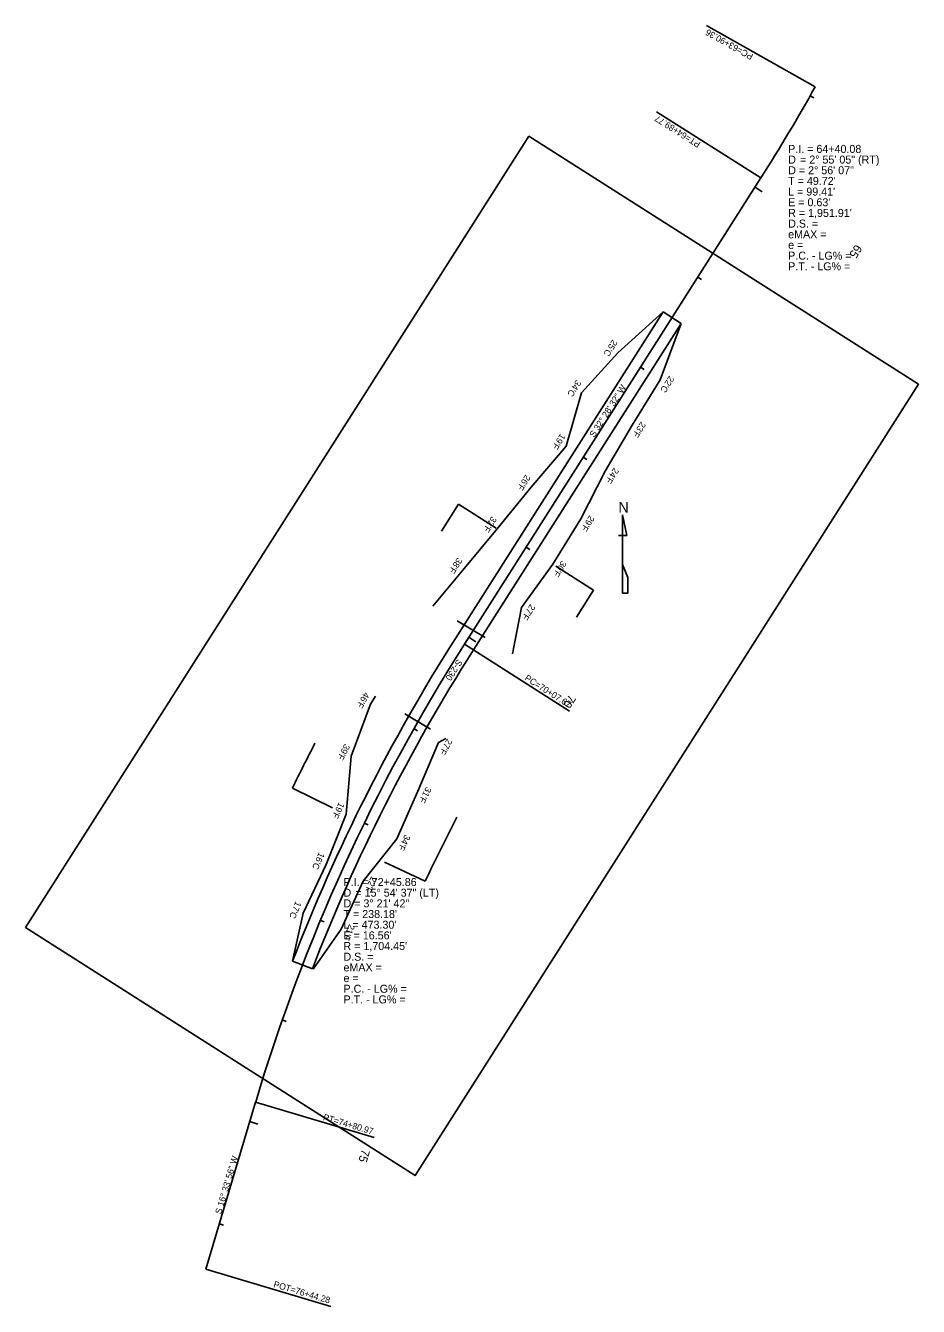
# Model space of a CAD drawing. Extents: x 1622419 to 1631737, y 887848 to 892020.
# Drawn here: x 1630900 to 1631737, y 887848 to 889048 of the extents above; entities that cross this region are included whole.
import ezdxf

# ---------------------------------------------------------------- set-up
doc = ezdxf.new("R2010")
doc.units = 0
for name, color, linetype in [('GN_Clip', 7, 'Continuous'), ('RD_EX_Misc', 7, 'Continuous'), ('RD_HC_Cl', 7, 'Continuous'), ('RD_HC_Data', 7, 'Continuous'), ('RD_HC_Data_Tic', 7, 'Continuous'), ('RD_HC_TX_Sta50', 7, 'Continuous'), ('RD_PD_Bridge', 7, 'Continuous'), ('RD_PD_CstnLmt', 7, 'Continuous'), ('RD_PD_CstnLmt_TX', 7, 'Continuous'), ('RD_PD_Final_TrvlWay', 7, 'Continuous'), ('RD_PD_RW', 7, 'Continuous'), ('RD_TX_RoadID', 7, 'Continuous')]:
    doc.layers.add(name, color=color, linetype=linetype)

msp = doc.modelspace()

# ---------------------------------------------------------------- linework, layer by layer
at = {"layer": 'GN_Clip'}
msp.add_lwpolyline([(1630899.9, 888203), (1631371.9, 888944.6), (1631737.1, 888712.2), (1631265.1, 887970.6)], close=True, dxfattribs=at)
at = {"layer": 'RD_EX_Misc'}
for p, q in [((1631463.7, 888570.4), (1631459.7, 888590)), ((1631459.7, 888590), (1631459.7, 888590)), ((1631459.7, 888590), (1631459.7, 888570.4)), ((1631455.8, 888570.4), (1631459.7, 888570.4)), ((1631459.7, 888543.2), (1631459.7, 888570.4)), ((1631459.7, 888570.4), (1631463.7, 888570.4)), ((1631463.7, 888570.4), (1631463.7, 888570.6)), ((1631464.6, 888531.2), (1631459.7, 888543.2)), ((1631459.7, 888543.2), (1631459.7, 888516.5)), ((1631464.6, 888516.5), (1631464.6, 888531.3)), ((1631464.6, 888531.3), (1631464.6, 888531.2)), ((1631459.7, 888516.5), (1631464.6, 888516.5))]:
    msp.add_line(p, q, dxfattribs=at)
at = {"layer": 'RD_HC_Cl'}
for p, q in [((1631589.5, 888905.6), (1631311.4, 888468.7)), ((1631115.6, 888039.4), (1631069, 887882.9))]:
    msp.add_line(p, q, dxfattribs=at)
for centre, radius, start, end in [((1629939.7, 889948.8), 1951.9, 327.6913, 330.6095), ((1632749.3, 887553.5), 1704.4, 147.5244, 163.4346)]:
    msp.add_arc(centre, radius, start, end, dxfattribs=at)
at = {"layer": 'RD_HC_Data'}
for p, q in [((1631640.4, 888990.9), (1631538.5, 889048.3)), ((1631589.5, 888905.6), (1631491.4, 888967.5)), ((1631311.4, 888468.7), (1631410, 888405.9)), ((1631115.6, 888039.4), (1631226.7, 888006.4)), ((1631069, 887882.9), (1631186, 887848.1))]:
    msp.add_line(p, q, dxfattribs=at)
at = {"layer": 'RD_HC_Data_Tic'}
for p, q in [((1631635.7, 888982.5), (1631639.2, 888980.5)), ((1631584, 888896.9), (1631590.7, 888892.6)), ((1631530.3, 888812.6), (1631533.6, 888810.4)), ((1631476.6, 888728.2), (1631479.9, 888726.1)), ((1631422.9, 888643.9), (1631426.3, 888641.7)), ((1631369.2, 888559.5), (1631372.6, 888557.3)), ((1631315.5, 888475.1), (1631322.2, 888470.8)), ((1631263.9, 888389.5), (1631267.4, 888387.5)), ((1631217.5, 888300.9), (1631221.1, 888299.2)), ((1631176.3, 888209.8), (1631180, 888208.3)), ((1631140.5, 888116.5), (1631144.3, 888115.1)), ((1631110.2, 888021.2), (1631117.8, 888018.9)), ((1631081.6, 887925.3), (1631085.5, 887924.2))]:
    msp.add_line(p, q, dxfattribs=at)
at = {"layer": 'RD_PD_Bridge'}
for p, q in [((1631304.6, 888490.6), (1631330.9, 888474.9)), ((1631255.4, 888403.5), (1631279.6, 888389))]:
    msp.add_line(p, q, dxfattribs=at)
at = {"layer": 'RD_PD_CstnLmt'}
for p, q in [((1631497.7, 888780), (1631455.3, 888741.8)), ((1631514.5, 888769.2), (1631495, 888716.5)), ((1631455.3, 888741.8), (1631421.3, 888704.1)), ((1631495, 888716.5), (1631468.8, 888673.9)), ((1631421.3, 888704.1), (1631406.7, 888654.1)), ((1631468.8, 888673.9), (1631443.5, 888630.8)), ((1631406.7, 888654.1), (1631374, 888615.7)), ((1631443.5, 888630.8), (1631420.5, 888586.1)), ((1631374, 888615.7), (1631342.2, 888576.6)), ((1631420.5, 888586.1), (1631394.2, 888543.5)), ((1631342.2, 888576.6), (1631310, 888537.9)), ((1631310, 888537.9), (1631281.8, 888504.2)), ((1631394.2, 888543.5), (1631365, 888502.9)), ((1631365, 888502.9), (1631356.4, 888459.7)), ((1631227.9, 888419.9), (1631223.4, 888412.3)), ((1631223.4, 888412.3), (1631205.3, 888363.8)), ((1631287.2, 888376.4), (1631267.7, 888331)), ((1631294, 888380.4), (1631287.2, 888376.4)), ((1631205.3, 888363.8), (1631200.4, 888309.3)), ((1631267.7, 888331), (1631247.9, 888286.1)), ((1631200.4, 888309.3), (1631181.8, 888262.2)), ((1631247.9, 888286.1), (1631216.4, 888246.6)), ((1631181.8, 888262.2), (1631160.3, 888216.5)), ((1631216.4, 888246.6), (1631195.9, 888201.6)), ((1631160.3, 888216.5), (1631150.2, 888171.7)), ((1631169.4, 888164.2), (1631195.9, 888201.6))]:
    msp.add_line(p, q, dxfattribs=at)
at = {"layer": 'RD_PD_Final_TrvlWay'}
for p, q in [((1631497.7, 888780), (1631302.9, 888474)), ((1631497.7, 888780), (1631514.5, 888769.2)), ((1631514.5, 888769.2), (1631319.8, 888463.3)), ((1631150.2, 888171.7), (1631168.8, 888164.5))]:
    msp.add_line(p, q, dxfattribs=at)
for radius in [1714.4, 1694.4]:
    msp.add_arc((1632749.3, 887553.5), radius, 147.5244, 158.8638, dxfattribs=at)
at = {"layer": 'RD_PD_RW'}
for p, q in [((1631305.9, 888599.8), (1631289.8, 888574.5)), ((1631341.3, 888577.2), (1631305.9, 888599.8)), ((1631397, 888541.8), (1631432.5, 888519.2)), ((1631432.5, 888519.2), (1631416.4, 888493.9)), ((1631150.1, 888333.8), (1631187.8, 888315.4)), ((1631274.5, 888246.5), (1631236.5, 888264.3))]:
    msp.add_line(p, q, dxfattribs=at)
for radius, end in [(1779.4, 153.9895), (1629.4, 154.8299)]:
    msp.add_arc((1632749.3, 887553.5), radius, 152.4785, end, dxfattribs=at)

# ---------------------------------------------------------------- texts
at = {"layer": 'RD_EX_Misc'}
msp.add_text('N', height=10, dxfattribs=at).set_placement((1631455.8, 888591.9))
at = {"layer": 'RD_HC_Data'}
for s, rotation, p in [('PC=63+90.36', 150.6095, (1631582.8, 889021.1)), ('PT=64+89.77', 147.6913, (1631533.4, 888938.6)), ('S 32%%d 28\' 32" W', 57.5244, (1631433.2, 888661.9)), ('PC=70+07.67', 327.5244, (1631367.3, 888435.4)), ('PT=74+80.97', 343.4346, (1631178.4, 888022.8)), ('S 16%%d 33\' 56" W', 73.4346, (1631083.2, 887934.1)), ('POT=76+44.28', 343.4346, (1631131.9, 887866.3))]:
    msp.add_text(s, height=6, rotation=rotation, dxfattribs=at).set_placement(p)
for s, p in [('P.I. = 64+40.08', (1631615, 888929)), ('D', (1631615, 888919)), ('    = 2%%d 55\' 05" (RT)', (1631615, 888919)), ('D = 2%%d 56\' 07"', (1631615, 888909)), ("T = 49.72'", (1631615, 888899)), ("L = 99.41'", (1631615, 888889)), ("E = 0.63'", (1631615, 888879)), ("R = 1,951.91'", (1631615, 888869)), ('D.S. = ', (1631615, 888859)), ('eMAX = ', (1631615, 888849)), ('e = ', (1631615, 888839)), ('P.C. - LG% = ', (1631615, 888829)), ('P.T. - LG% = ', (1631615, 888819)), ('P.I. = 72+45.86', (1631198, 888242)), ('D', (1631198, 888232)), ('    = 15%%d 54\' 37" (LT)', (1631198, 888232)), ('D = 3%%d 21\' 42"', (1631198, 888222)), ("T = 238.18'", (1631198, 888212)), ("L = 473.30'", (1631198, 888202)), ("E = 16.56'", (1631198, 888192)), ("R = 1,704.45'", (1631198, 888182)), ('D.S. = ', (1631198, 888172)), ('eMAX = ', (1631198, 888162)), ('e = ', (1631198, 888152)), ('P.C. - LG% = ', (1631198, 888142)), ('P.T. - LG% = ', (1631198, 888132))]:
    msp.add_text(s, height=7.5, dxfattribs=at).set_placement(p)
at = {"layer": 'RD_HC_TX_Sta50'}
for s, rotation, p in [('65', 237.5244, (1631678.2, 888843.8)), ('70', 237.5244, (1631409.7, 888422)), ('75', 253.4346, (1631215.3, 887995.9))]:
    msp.add_text(s, height=8, rotation=rotation, dxfattribs=at).set_placement(p)
at = {"layer": 'RD_PD_CstnLmt_TX'}
for s, rotation, p in [("25'C", 237.5244, (1631450.3, 888754.5)), ("22'C", 237.5244, (1631503.5, 888720.6)), ("34'C", 237.5244, (1631416.3, 888716.8)), ("23'F", 237.5244, (1631477, 888677.6)), ("19'F", 237.5244, (1631401.5, 888666.4)), ("24'F", 237.5244, (1631451.7, 888634.5)), ("26'F", 237.5244, (1631368.8, 888628)), ("32'F", 237.5244, (1631337, 888588.9)), ("29'F", 237.5244, (1631428.8, 888589.8)), ("38'F", 237.5244, (1631304.8, 888550.2)), ("30'F", 237.5244, (1631402.5, 888547.2)), ("27'F", 237.5244, (1631373.2, 888506.6)), ("46'F", 240.628, (1631217.6, 888424.2)), ("39'F", 242.3087, (1631199.1, 888375.6)), ("27'F", 240.628, (1631295.2, 888380.5)), ("31'F", 242.3087, (1631275.6, 888335.4)), ("19'F", 243.9895, (1631193.8, 888320.9)), ("34'F", 243.9895, (1631255.7, 888290.7)), ("16'C", 245.6703, (1631175.1, 888274)), ("22'F", 245.6703, (1631224, 888251.4)), ("17'C", 247.3511, (1631153.2, 888228.1)), ("21'F", 247.3511, (1631203.4, 888206.7))]:
    msp.add_text(s, height=6, rotation=rotation, dxfattribs=at).set_placement(p)
at = {"layer": 'RD_TX_RoadID'}
msp.add_text('S-230', height=6, rotation=237.5244, dxfattribs=at).set_placement((1631304.9, 888455))

doc.saveas('drawing.dxf')
